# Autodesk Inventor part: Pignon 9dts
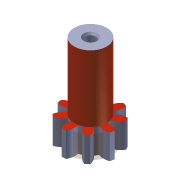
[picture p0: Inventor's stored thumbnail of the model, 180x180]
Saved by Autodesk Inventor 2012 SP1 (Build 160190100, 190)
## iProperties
Created: 2014-12
Part Number: Pignon 9dts
Material: Default
Document SubType Name: Modeling
Designer: Bruno
Density: 1 g/cm^3
Mass: 2.6379 g
Surface Area: 16.4372 cm^2
Volume: 2.6379 cm^3
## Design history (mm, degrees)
node "Pignon 9dts1"
sketch "Esquisse1"
  geometry: C1 r 2.048 at (0, 0) reference; C2 r 6.75 at (0, 0)
  constraints: 1 centre point, 1 coincident
  dimensions: "d2" = 13.5 diameter of C2
feature "SrfExtrusion1" sketch "Esquisse1" dims "d0" = 7, "d1" = 0
node "Pignon 9dts"
node "Base1"
body "Srf1"
